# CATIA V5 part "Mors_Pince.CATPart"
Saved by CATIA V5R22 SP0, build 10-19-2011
Part number: Mors
Bounding box of the stored display mesh (mm): x -6 to 6, y -26 to 20, z -10 to 10
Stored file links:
  D:\PER\CAO_PER_MODIF_2025\CAO_PER_pick&place_2024P\Cadre\Chariot_Y\Prehenseur\Mors_Pince.CATPart
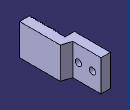
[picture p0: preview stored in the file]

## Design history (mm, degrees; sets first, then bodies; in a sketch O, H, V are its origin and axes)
Body1 (main body)
  Sketch1 on xy-plane, origin (0, 0, 0), H (1, 0, 0), V (0, 1, 0)
    line L1 (-6, 20) -> (0, 20)
    line L2 (0, 20) -> (0, 0)
    line L3 (-6, -3) -> (-6, 20)
    point P3 (0, 0)
    point P4 (-6, -3)
    line L4 (0, -3) -> (-6, -3)
    point P5 (0, 0)
    point P7 (-6, -3)
    line L5 (0, 0) -> (6, 0)
    line L6 (6, 0) -> (6, -26)
    line L7 (6, -26) -> (0, -26)
    line L8 (0, -26) -> (0, -3)
    point P11 (-3.4793, -30.014)
    distance L2 L3 = 6
    distance L6 L8 = 6
    distance L5 L4 = 3
    distance L8 L3 = 6
    distance L4 L7 = 23
    length L2 = 20
    horizontal: L1 H, L4 H, L5 H, L7 H
    vertical: L2 V, L3 V, L6 V, L8 V
    coincidence: P5 P3, P4 P7, L2 V, L5 H
  Pad1: profile Sketch1, direction (0, 0, 1), length 10, mirrored extent
  Sketch2 on yz-plane, origin (0, 0, 0), H (0, 1, 0), V (0, 0, 1)
    point P1 (15, 4.5)
    point P2 (15, -4.5)
    reference projected line E1 (20, -10) -> (20, 10) from edge [face of Pad1 from Sketch1.L1 | face of Pad1 from Sketch1.L2]
    distance P1 P2 = 9
    distance P1 E1 = 5
    symmetry: P2 P1 H
  Sketch3 on face of Pad1 from Sketch1.L2, origin (0, 5, 4.5), H (0, 1, 0), V (0, 0, 1)
    point P1 (9.5, -4.5)
    reference projected line E1 (15, -14.5) -> (15, 5.5) from edge [face of Pad1 from Sketch1.L1 | face of Pad1 from Sketch1.L2]
    reference projected line E2 (-5, 5.5) -> (15, 5.5) from edge [face of Pad1 from Sketch1.L2 | end face of Pad1]
    reference projected line E3 (-5, -14.5) -> (15, -14.5) from edge [start face of Pad1 | face of Pad1 from Sketch1.L2]
    reference projected line E4 (-5, 5.5) -> (15, 5.5) from edge [face of Pad1 from Sketch1.L2 | end face of Pad1]
    distance P1 E1 = 5.5
    distance E2 E3 = 20 (reference)
    distance P1 E4 = 10
  Hole1: placed by Sketch3, at (0, 14.5, 0) direction (-1, 0, 0), diameter 4, depth 10
  Chamfer1: length 2, second length 6, on edge [face of Pad1 from Sketch1.L2 | face of Pad1 from Sketch1.L5]
  Sketch4 on xy-plane, origin (0, 0, 0), H (1, 0, 0), V (0, 1, 0)
    line L1 (0, -24.5858) -> (-0.7071, -25.2929)
    point P1 (0, -24.5858)
    line L2 (-0.7071, -25.2929) -> (0, -26)
    point P3 (0, -26)
    reference projected point E1 (0, -26) from vertex [face of Pad1 from Sketch1.L7 | end face of Pad1 | face of Pad1 from Sketch1.L8]
    line L3 (0, -24.5858) -> (0, -26)
    reference projected line E2 (0, -3) -> (0, -26) from edge [face of Pad1 from Sketch1.L8 | end face of Pad1]
    length L2 = 1
    length L1 = 1
    perpendicularity: L2 L1
    coincidence: P3 E1, P1 E2
  Pad2: profile Sketch4, direction (0, 0, 1), length 10, mirrored extent
  RectPattern1: of Pad2, direction 1 instances 13, spacing 1.42, along edge [face of Pad1 from Sketch1.L8 | face of Pad2] reversed
  Sketch5 on face of Pad1 from Sketch1.L2, origin (0, 8.2163, 0.9815), H (0, 1, 0), V (0, 0, 1)
    point P1 (-2.7163, -0.9815)
    reference projected line E1 (-6.2163, 9.0185) -> (-6.2163, -10.9815) from edge [face of Chamfer1 | face of Pad1 from Sketch1.L2]
    reference projected line E2 (-6.2163, 9.0185) -> (11.7837, 9.0185) from edge [face of Pad1 from Sketch1.L2 | face of RectPattern1]
    distance P1 E1 = 3.5
    distance P1 E2 = 10
  Hole2: placed by Sketch5, at (0, 5.5, 0) direction (-1, 0, 0), diameter 4, depth 10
